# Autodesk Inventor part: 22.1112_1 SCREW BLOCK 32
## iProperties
Created: 2007-04
Part Number: 22.1112_1 SCREW BLOCK 32
Material: ABS Plastic
Document SubType Name: Modeling
Designer: Andy Moles
Mass: 6.34788 g
Surface Area: 42.2156 cm^2
Volume: 5.98857 cm^3
Density: 1.06 g/cm^3
Author: Andy Moles
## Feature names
1. Base1
